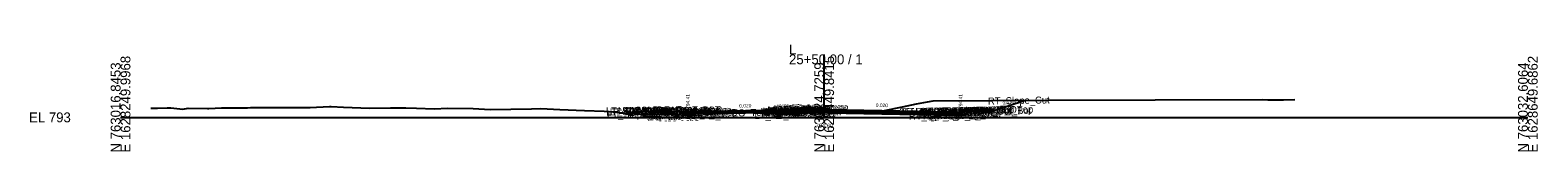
# Model space of a CAD drawing. Extents: x -26 to 4403, y -510 to 9556.
# Drawn here: x 974.3 to 1402.8, y 5490.3 to 5520.7 of the extents above; entities that cross this region are included whole.
import ezdxf

# ---------------------------------------------------------------- set-up
doc = ezdxf.new("R2010")
doc.units = 0
for name, color, linetype in [('Default', 7, 'Continuous'), ('Exist CMT Pavement', 7, 'Continuous'), ('Exist Cross Section Cell', 7, 'Continuous'), ('Exist XS Center Line Elevation Label', 7, 'Continuous'), ('Exist XS Ground Line', 7, 'Continuous'), ('Prop CMT Conc Surface', 7, 'Continuous'), ('Prop CMT Concrete Structures', 7, 'Continuous'), ('Prop CMT Pvmt Course 1', 7, 'Continuous'), ('Prop CMT Pvmt Course 1 CG', 7, 'Continuous'), ('Prop CMT Pvmt Course 1 Wedge', 7, 'Continuous'), ('Prop CMT Pvmt Course 2', 7, 'Continuous'), ('Prop CMT Pvmt Course 2 Wedge', 7, 'Continuous'), ('Prop CMT Pvmt Course 3', 7, 'Continuous'), ('Prop CMT Pvmt Course 3 Wedge', 7, 'Continuous'), ('Prop CMT Pvmt Surface', 7, 'Continuous'), ('Prop CMT Pvmt Wedge Surface 1', 7, 'Continuous'), ('Prop CMT Pvmt Wedge Surface 2', 7, 'Continuous'), ('Prop CMT Pvmt Wedge Surface 3', 7, 'Continuous'), ('Prop CMT Slope Grass', 7, 'Continuous'), ('Prop CMT Subgrade Earthwork', 7, 'Continuous'), ('Prop XS Hydro Elevations', 7, 'Continuous'), ('Prop XS SE Text', 7, 'Continuous'), ('Prop XS Side Slope Text', 7, 'Continuous'), ('Scratch_Level_0', 7, 'Continuous')]:
    doc.layers.add(name, color=color, linetype=linetype)

msp = doc.modelspace()

# ---------------------------------------------------------------- linework, layer by layer
at = {"layer": 'Exist CMT Pavement'}
msp.add_lwpolyline([(1163.26, 5501.16), (1171.19, 5501.43), (1174.26, 5501.38), (1181.28, 5501.25), (1184.81, 5501.13), (1190.72, 5500.95)], dxfattribs=at)
at = {"layer": 'Exist Cross Section Cell'}
for p, q in [((1200, 5500), (1200, 5517.9)), ((1000, 5500), (1200, 5500)), ((1200, 5500), (1400, 5500))]:
    msp.add_line(p, q, dxfattribs=at)
at = {"layer": 'Exist XS Ground Line'}
msp.add_lwpolyline([(1008.63, 5502.61), (1010.46, 5502.62), (1013.28, 5502.72), (1014.32, 5502.7), (1017.66, 5502.36), (1019.18, 5502.59), (1024.69, 5502.55), (1025.07, 5502.54), (1028.72, 5502.67), (1030.95, 5502.7), (1036.1, 5502.75), (1036.89, 5502.76), (1044.38, 5502.78), (1047.02, 5502.79), (1053.87, 5502.83), (1059.36, 5503.08), (1059.9, 5503.08), (1063.38, 5502.86), (1070.76, 5502.62), (1076.74, 5502.69), (1081.1, 5502.67), (1084.14, 5502.61), (1089.18, 5502.41), (1093.03, 5502.59), (1100.22, 5502.48), (1105.08, 5502.24), (1116.85, 5502.45), (1119.49, 5502.53), (1124.82, 5502.23), (1131.83, 5501.92), (1137.46, 5501.72), (1138.88, 5501.65), (1145.07, 5501.09), (1146.64, 5500.98), (1147.58, 5500.94), (1148.46, 5500.85), (1149.51, 5500.84), (1149.84, 5500.68), (1156.03, 5500.91), (1171.19, 5501.43), (1174.26, 5501.38), (1181.28, 5501.25), (1184.81, 5501.13), (1190.72, 5500.95), (1191.66, 5500.81), (1192.69, 5500.73), (1193, 5500.93), (1193.34, 5501.17), (1195.6, 5501.35), (1197.2, 5501.49), (1199.35, 5501.6), (1200, 5501.6), (1201.57, 5501.6), (1204.35, 5501.6), (1211.4, 5501.32), (1212.61, 5501.23), (1217.15, 5501.97), (1222.23, 5503.02), (1226.26, 5503.85), (1229.36, 5504.37), (1230.97, 5504.68), (1263.65, 5504.87), (1324.47, 5505.12), (1326.09, 5505), (1326.88, 5505), (1330.59, 5505.03), (1333.79, 5505.07)], dxfattribs=at)
at = {"layer": 'Prop CMT Conc Surface'}
for points in [[(1163.25, 5501.53), (1161.25, 5501.41)], [(1236.75, 5501.53), (1238.75, 5501.41)], [(1238.75, 5501.41), (1238.75, 5501.91), (1239.25, 5501.91)], [(1243.25, 5502), (1248.25, 5502.1)]]:
    msp.add_lwpolyline(points, dxfattribs=at)
at = {"layer": 'Prop CMT Concrete Structures'}
for p, q in [((1146.25, 5501.59), (1143.72, 5501.21)), ((1151.25, 5501.79), (1146.25, 5501.59)), ((1156.75, 5501.68), (1151.25, 5501.79)), ((1160.75, 5501.52), (1156.75, 5501.68)), ((1161.25, 5501.41), (1160.75, 5501.52))]:
    msp.add_line(p, q, dxfattribs=at)
for points in [[(1196, 5502.34), (1195.99, 5502.51), (1195.24, 5502.76), (1194, 5502.78), (1192.76, 5502.52), (1192.01, 5502.27), (1192, 5502.1)], [(1151.75, 5501.45), (1151.75, 5501.78)], [(1156.75, 5501.35), (1151.75, 5501.45)], [(1156.75, 5501.68), (1156.75, 5501.35)], [(1160.75, 5501.52), (1160.75, 5500.89), (1163.25, 5500.95)], [(1163.25, 5501.53), (1161.25, 5501.41)], [(1163.25, 5500.95), (1163.25, 5501.53)], [(1192, 5502.1), (1196, 5502.34)], [(1236.75, 5501.53), (1238.75, 5501.41), (1238.75, 5501.91), (1239.25, 5501.91)], [(1239.25, 5501.91), (1239.25, 5500.89), (1236.75, 5500.95)], [(1236.75, 5500.95), (1236.75, 5501.53)], [(1248.25, 5502.1), (1243.25, 5502)], [(1243.25, 5502), (1243.25, 5501.66)], [(1243.25, 5501.66), (1248.25, 5501.76)], [(1248.25, 5501.76), (1248.25, 5502.1)]]:
    msp.add_lwpolyline(points, dxfattribs=at)
at = {"layer": 'Prop CMT Pvmt Course 1'}
for points in [[(1192, 5502.1), (1163.25, 5501.53)], [(1163.25, 5501.4), (1192, 5501.98)], [(1163.25, 5501.53), (1163.25, 5501.28), (1163.25, 5501.28), (1163.25, 5501.4)], [(1192, 5502.1), (1196, 5502.34)], [(1192, 5501.85), (1192, 5502.1)], [(1192, 5501.85), (1192, 5502.1)], [(1196, 5502.09), (1192, 5501.85)], [(1192, 5501.98), (1192, 5501.85), (1192, 5501.85)], [(1196, 5502.34), (1196, 5502.09)], [(1196, 5502.34), (1236.75, 5501.53)], [(1196, 5502.09), (1196, 5502.34)], [(1236.75, 5501.28), (1196, 5502.09)], [(1236.75, 5501.53), (1236.75, 5501.28)]]:
    msp.add_lwpolyline(points, dxfattribs=at)
msp.add_lwpolyline([(1196, 5502.09), (1196, 5502.22), (1196, 5502.22), (1196, 5502.09)], close=True, dxfattribs=at)
at = {"layer": 'Prop CMT Pvmt Course 1 CG'}
for points in [[(1163.25, 5500.95), (1160.25, 5500.88), (1159.91, 5500.54)], [(1159.91, 5500.54), (1163.25, 5500.61)], [(1163.25, 5500.61), (1163.25, 5500.95)], [(1236.75, 5500.95), (1239.75, 5500.88), (1240.09, 5500.54)], [(1236.75, 5500.61), (1236.75, 5500.95)], [(1240.09, 5500.54), (1236.75, 5500.61)]]:
    msp.add_lwpolyline(points, dxfattribs=at)
at = {"layer": 'Prop CMT Pvmt Course 1 Wedge'}
for points in [[(1163.25, 5501.4), (1171.19, 5501.56), (1174.26, 5501.62), (1181.28, 5501.76), (1184.81, 5501.83), (1190.72, 5501.95), (1191.66, 5501.97), (1192, 5501.98)], [(1192, 5501.85), (1191.66, 5501.85), (1190.72, 5501.83), (1184.81, 5501.71), (1181.28, 5501.64), (1174.26, 5501.5), (1171.19, 5501.44), (1163.25, 5501.28)], [(1163.25, 5501.28), (1163.25, 5501.4)], [(1192, 5501.98), (1192, 5501.85)]]:
    msp.add_lwpolyline(points, dxfattribs=at)
at = {"layer": 'Prop CMT Pvmt Course 2'}
for points in [[(1163.25, 5500.95), (1163.25, 5500.95), (1163.25, 5501.28), (1163.25, 5501.28)], [(1163.25, 5501.28), (1163.25, 5500.95)], [(1192, 5501.85), (1196, 5502.09)], [(1192, 5501.52), (1192, 5501.85)], [(1196, 5501.76), (1192, 5501.52)], [(1196, 5502.09), (1196, 5501.76)], [(1196, 5501.76), (1196, 5502.09)], [(1196, 5502.09), (1236.75, 5501.28)], [(1236.75, 5500.95), (1196, 5501.76)], [(1236.75, 5501.28), (1236.75, 5500.95)]]:
    msp.add_lwpolyline(points, dxfattribs=at)
at = {"layer": 'Prop CMT Pvmt Course 2 Wedge'}
for points in [[(1163.25, 5501.28), (1171.19, 5501.44), (1174.26, 5501.5), (1181.28, 5501.64), (1184.81, 5501.71), (1190.72, 5501.83), (1191.66, 5501.85), (1192, 5501.85)], [(1192, 5501.52), (1191.66, 5501.51), (1190.72, 5501.49), (1184.81, 5501.38), (1181.28, 5501.31), (1179.86, 5501.28), (1174.26, 5501.38), (1171.19, 5501.43), (1163.25, 5501.16)], [(1163.25, 5501.16), (1163.25, 5501.28)], [(1192, 5501.85), (1192, 5501.52)]]:
    msp.add_lwpolyline(points, dxfattribs=at)
at = {"layer": 'Prop CMT Pvmt Course 3'}
for points in [[(1163.25, 5500.95), (1163.25, 5500.95), (1163.25, 5500.61), (1163.25, 5500.61)], [(1163.25, 5500.61), (1163.25, 5500.95)], [(1192, 5501.52), (1196, 5501.76)], [(1192, 5501.19), (1192, 5501.52)], [(1196, 5501.43), (1192, 5501.19)], [(1196, 5501.76), (1196, 5501.43)], [(1196, 5501.76), (1236.75, 5500.95)], [(1196, 5501.43), (1196, 5501.76)], [(1236.75, 5500.61), (1196, 5501.43)], [(1236.75, 5500.95), (1236.75, 5500.61)]]:
    msp.add_lwpolyline(points, dxfattribs=at)
at = {"layer": 'Prop CMT Pvmt Course 3 Wedge'}
for points in [[(1179.85, 5501.28), (1181.28, 5501.31)], [(1192, 5500.79), (1191.66, 5500.81), (1190.72, 5500.95), (1184.81, 5501.13), (1181.28, 5501.25), (1179.85, 5501.28)], [(1181.28, 5501.31), (1184.81, 5501.38), (1190.72, 5501.49), (1191.66, 5501.51), (1192, 5501.52)]]:
    msp.add_lwpolyline(points, dxfattribs=at)
at = {"layer": 'Prop CMT Pvmt Surface'}
for points in [[(1192, 5502.1), (1163.25, 5501.53)], [(1192, 5502.1), (1196, 5502.34)], [(1196, 5502.34), (1236.75, 5501.53)]]:
    msp.add_lwpolyline(points, dxfattribs=at)
at = {"layer": 'Prop CMT Pvmt Wedge Surface 1'}
for points in [[(1192, 5501.98), (1163.25, 5501.4)], [(1163.25, 5501.28), (1163.25, 5501.53)], [(1163.25, 5501.4), (1163.25, 5501.28), (1163.25, 5501.28)], [(1192, 5502.1), (1192, 5501.85), (1192, 5501.85), (1192, 5501.98)]]:
    msp.add_lwpolyline(points, dxfattribs=at)
at = {"layer": 'Prop CMT Pvmt Wedge Surface 2'}
for points in [[(1192, 5501.85), (1163.25, 5501.28)], [(1163.25, 5501.28), (1163.25, 5501.53)], [(1192, 5502.1), (1192, 5501.85)]]:
    msp.add_lwpolyline(points, dxfattribs=at)
at = {"layer": 'Prop CMT Pvmt Wedge Surface 3'}
for points in [[(1163.25, 5500.95), (1163.25, 5501.53)], [(1192, 5501.52), (1163.25, 5500.95)], [(1192, 5502.1), (1192, 5501.52)]]:
    msp.add_lwpolyline(points, dxfattribs=at)
at = {"layer": 'Prop CMT Slope Grass'}
for points in [[(1248.25, 5502.09), (1248.75, 5502.1), (1256.95, 5504.83)], [(1239.25, 5501.91), (1248.25, 5502.09)]]:
    msp.add_lwpolyline(points, dxfattribs=at)
at = {"layer": 'Prop CMT Subgrade Earthwork'}
msp.add_line((1190.72, 5501.16), (1190.72, 5500.95), dxfattribs=at)
for points in [[(1163.25, 5500.61), (1159.91, 5500.54), (1158.86, 5501.59)], [(1163.25, 5500.61), (1163.26, 5501.16)], [(1163.25, 5500.61), (1163.25, 5500.61)], [(1190.72, 5501.16), (1190.72, 5501.16), (1191.66, 5501.18), (1192, 5501.19)], [(1192, 5501.19), (1196, 5501.43)], [(1196, 5501.43), (1236.75, 5500.61)], [(1236.75, 5500.61), (1240.09, 5500.54), (1241.5, 5501.95)]]:
    msp.add_lwpolyline(points, dxfattribs=at)

# ---------------------------------------------------------------- texts
at = {"layer": 'Default'}
msp.add_text('-', height=0.0001, dxfattribs=at).set_placement((1000, 5500))
at = {"layer": 'Exist Cross Section Cell'}
for s, p in [('L', (1190, 5517.9)), ('25+50.00 / 1', (1190, 5515.1)), ('EL 793', (974, 5498.6))]:
    msp.add_text(s, height=2.8, dxfattribs=at).set_placement(p)
for s, p in [('N 763016.8453', (1000, 5490)), ('E 1628249.9968', (1002.8, 5490)), ('N 763024.7259', (1200, 5490)), ('E 1628449.8415', (1202.8, 5490)), ('N 763032.6064', (1400, 5490)), ('E 1628649.6862', (1402.8, 5490))]:
    msp.add_text(s, height=2.8, rotation=90, dxfattribs=at).set_placement(p)
at = {"layer": 'Exist XS Center Line Elevation Label'}
msp.add_text('794.60', height=1.2, dxfattribs=at).set_placement((1197.52, 5497))
at = {"layer": 'Prop XS Hydro Elevations'}
for p in [(1161.75, 5502.41), (1239.25, 5502.41)]:
    msp.add_text('794.41', height=1, rotation=90, dxfattribs=at).set_placement(p)
at = {"layer": 'Prop XS SE Text'}
for s, rotation, p in [('15.00%', 8.5308, (1141.27, 5501.19)), ('4.00%', 2.2906, (1146.99, 5501.85)), ('2.00%', 358.8542, (1152.4, 5501.96)), ('4.00%', 357.7094, (1156.62, 5502)), ('0.020', 1.1458, (1175.86, 5502.78)), ('0.020', 358.8542, (1214.65, 5502.97))]:
    msp.add_text(s, height=1, rotation=rotation, dxfattribs=at).set_placement(p)
at = {"layer": 'Prop XS Side Slope Text'}
msp.add_text('3:1', height=1, rotation=18.4349, dxfattribs=at).set_placement((1250.92, 5503.4))
at = {"layer": 'Scratch_Level_0'}
for s, p in [('LT_SDWK_Out_Top', (1138.01, 5500.82)), ('LT_SDWK_Out_Bot', (1138.04, 5500.49)), ('LT_Sub_Trench_Out_DLT', (1139.09, 5500.56)), ('LT_CSLP_Pnt', (1141.44, 5500.9)), ('25+50.00', (1143.72, 5500.7)), ('LT_SDWK_In_Top', (1144.63, 5500.76)), ('LT_SDWK_In_Bot', (1144.66, 5500.42)), ('LT_CG_Top_Face', (1148.53, 5500.65)), ('LT_CG_Top_BOC', (1149.05, 5500.67)), ('LT_CG_Top_Gut', (1149.51, 5500.17)), ('LT_PV_OEEOP_EG', (1150.82, 5499.91)), ('LT_PV2_OEEOP', (1152.58, 5500.06)), ('25+50.00', (1152.89, 5500.8)), ('LT_PV1_OEEOP', (1153.15, 5500.2)), ('LT_PV2_OEOT', (1153.45, 5500.08)), ('LT_PV1_OEOT', (1154.01, 5500.34)), ('25+50.00', (1154.89, 5500.3)), ('LT_PV_EG_TestPt', (1164.06, 5500.04)), ('LT_PV2_IEEOP', (1181.98, 5500.65)), ('LT_PV3_IEEOP', (1181.98, 5500.32)), ('LT_PV1_IEEOP', (1182.54, 5500.79)), ('LT_PV2_PGL1', (1182.9, 5500.67)), ('LT_PV3_PGL1', (1182.9, 5500.34)), ('LT_PV2_PGL', (1183.23, 5500.68)), ('LT_PV3_PGL', (1183.23, 5500.34)), ('LT_PV1_PGL', (1183.8, 5500.94)), ('MI_Face In', (1183.92, 5501.11)), ('RT_Sub_OEEOP', (1185.19, 5500.21)), ('25+50.00', (1185.27, 5501.11)), ('RT_PV2_OEEOP', (1185.28, 5500.88)), ('RT_PV3_OEEOP', (1185.28, 5500.55)), ('25+50.00', (1185.37, 5501.17)), ('MI_Top In', (1185.63, 5501.38)), ('RT_PV1_OEEOP', (1185.85, 5501.01)), ('RT_PV2_IEEOP', (1185.93, 5500.89)), ('MI_Face Out', (1186.28, 5501.32)), ('MI_Top Out', (1186.49, 5501.58)), ('RT_PV1_IEEOP', (1186.49, 5501.03)), ('25+50.00', (1186.61, 5501.51)), ('RT_PV2_PGL1', (1186.86, 5500.91)), ('RT_PV3_PGL1', (1186.86, 5500.58)), ('MI_Crown', (1187.09, 5501.65)), ('RT_PV2_PGL', (1187.19, 5500.92)), ('RT_PV4_PGL', (1187.19, 5500.25)), ('MI_Bot Out', (1187.28, 5501.17)), ('RT_PV1_PGL', (1187.75, 5501.18)), ('25+50.00', (1189.06, 5501.44)), ('25+50.00', (1189.26, 5501.33)), ('25+50.00', (1221.39, 5500.57)), ('RT_Sub_Trench_Out_DLT', (1222.04, 5500.56)), ('RT_CG_Top_Face', (1225.99, 5500.65)), ('RT_PV2_OEOT', (1226.9, 5500.08)), ('RT_CG_Top_Gut', (1226.96, 5500.17)), ('RT_PV1_OEOT', (1227.46, 5500.34)), ('RT_CG_Top_BOC', (1227.51, 5500.67)), ('RT_SDWK_In_Top', (1231.08, 5500.75)), ('RT_SDWK_In_Bot', (1231.12, 5500.42)), ('25+50.00', (1232.19, 5500.77)), ('RT_SDWK_Out_Top', (1234.46, 5500.82)), ('RT_SDWK_Out_Bot', (1234.49, 5500.49)), ('RT_Shld_O', (1240.81, 5500.94)), ('25+50.00', (1241.61, 5500.96)), ('CSLP_Pnt', (1241.64, 5500.96)), ('RT_Slope_Cut', (1246.56, 5503.62)), ('LT_Slope_Fill', (1138.27, 5499.73)), ('LT_CG1_Shelf_Out', (1146.82, 5499.62)), ('LT_PV_Sub_Tie_Out', (1148.23, 5499.86)), ('LT_CG_Bot_BOC', (1149.09, 5499.66)), ('LT_Sub_OEOP', (1150.04, 5499.35)), ('LT_Sub_OEOT_CG', (1150.64, 5499.36)), ('LT_Sub_OEEOP', (1152.48, 5499.4)), ('LT_PV3_OEEOP', (1152.58, 5499.73)), ('LT_CG_Bot_IE', (1153.19, 5499.74)), ('LT_Sub_OEOT', (1153.35, 5499.41)), ('LT_PV3_OEOT', (1153.45, 5499.75)), ('LT_PV_IEEOP_EG', (1180.21, 5499.55)), ('LT_PV4_PGL', (1183.23, 5500.01)), ('RT_Sub_OEOT_CG', (1224.1, 5499.36)), ('RT_CG1_Shelf_Out', (1226.28, 5499.62)), ('RT_CG_Bot_IE', (1226.64, 5499.74)), ('RT_Sub_OEOT', (1226.8, 5499.41)), ('RT_PV3_OEOT', (1226.9, 5499.75)), ('RT_CG_Bot_BOC', (1227.54, 5499.66)), ('RT_Sub_OEOP', (1230.17, 5499.35))]:
    msp.add_text(s, height=2, rotation=1.1458, dxfattribs=at).set_placement(p)

doc.saveas('drawing.dxf')
